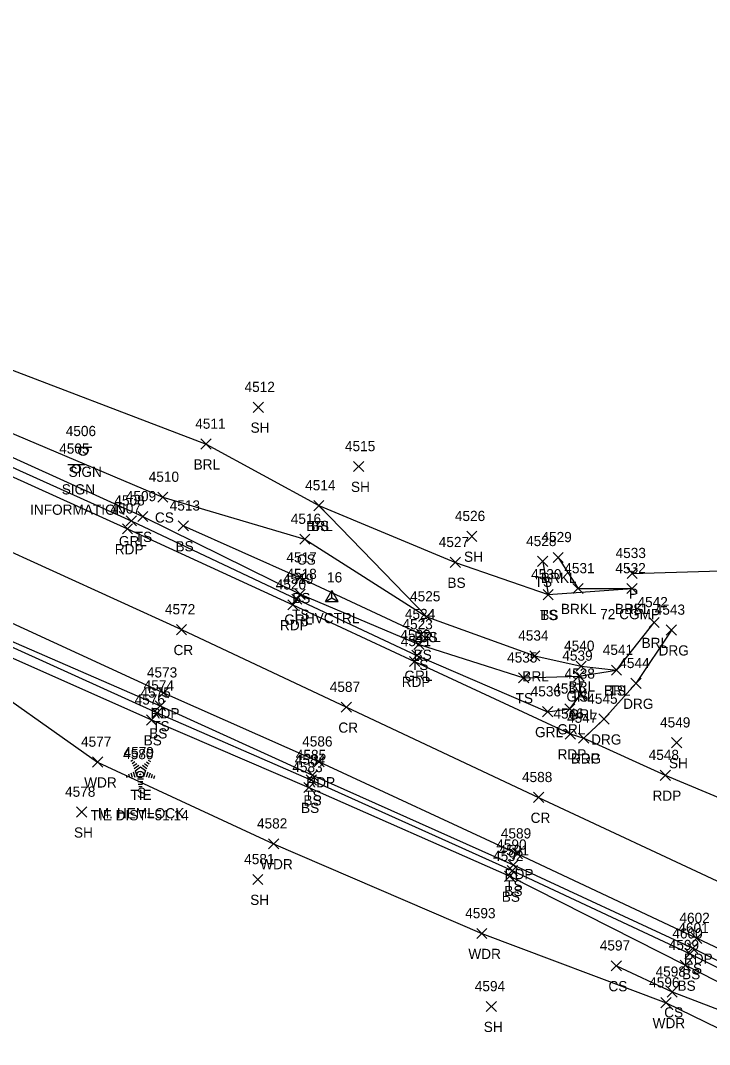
# Model space of a CAD drawing. Extents: x 1611797 to 1633212, y 298978 to 305475.
# Drawn here: x 1619568.2 to 1619703.4, y 301313.3 to 301514.2 of the extents above; entities that cross this region are included whole.
import ezdxf

# ---------------------------------------------------------------- set-up
doc = ezdxf.new("R2010")
doc.units = 0
for name, color, linetype in [('C_A', 7, 'Continuous'), ('C_C', 7, 'Continuous'), ('C_I', 7, 'Continuous'), ('CBP', 7, 'Continuous'), ('CPSM', 7, 'Continuous'), ('D_A', 7, 'Continuous'), ('D_C', 7, 'Continuous'), ('D_I', 7, 'Continuous'), ('D_TIC', 7, 'Continuous'), ('DCP', 7, 'Continuous'), ('L_A', 7, 'Continuous'), ('L_C', 7, 'Continuous'), ('L_I', 7, 'Continuous'), ('L_TIC', 7, 'Continuous'), ('LABL', 7, 'Continuous'), ('LAWA', 7, 'Continuous'), ('LAWE', 7, 'Continuous'), ('LELB', 7, 'Continuous'), ('LTC', 7, 'Continuous'), ('P_A', 7, 'Continuous'), ('P_I', 7, 'Continuous'), ('P_TIC', 7, 'Continuous'), ('PET', 7, 'Continuous'), ('PRC', 7, 'Continuous'), ('R_A', 7, 'Continuous'), ('R_I', 7, 'Continuous'), ('R_TIC', 7, 'Continuous'), ('RDG', 7, 'Continuous'), ('RGR', 7, 'Continuous'), ('S_A', 7, 'Continuous'), ('S_C', 7, 'Continuous'), ('S_I', 7, 'Continuous'), ('SSGN', 7, 'Continuous')]:
    doc.layers.add(name, color=color, linetype=linetype)

msp = doc.modelspace()

# ---------------------------------------------------------------- linework, layer by layer
at = {"layer": 'CBP'}
for radius in [0.625, 0.0833]:
    msp.add_circle((1619591.7, 301366.28), radius, dxfattribs=at)
at = {"layer": 'CPSM'}
for p, q in [((1619628.05, 301400.23), (1619629.3, 301402.39)), ((1619630.55, 301400.23), (1619629.3, 301402.39)), ((1619629.3, 301400.95), (1619629.3, 301402.39)), ((1619628.05, 301400.23), (1619629.3, 301400.95)), ((1619628.05, 301400.23), (1619630.55, 301400.23)), ((1619629.3, 301400.95), (1619629.3, 301400.95)), ((1619629.3, 301400.95), (1619630.55, 301400.23))]:
    msp.add_line(p, q, dxfattribs=at)
at = {"layer": 'D_TIC'}
for points in [[(1619687.22, 301404.73), (1619689.22, 301406.73)], [(1619689.22, 301404.73), (1619687.22, 301406.73)]]:
    msp.add_lwpolyline(points, dxfattribs=at)
at = {"layer": 'DCP'}
msp.add_lwpolyline([(1619688.22, 301405.73), (1619718.54, 301406.6)], dxfattribs=at)
at = {"layer": 'L_TIC'}
for points in [[(1619613.87, 301437.31), (1619615.87, 301439.31)], [(1619615.87, 301437.31), (1619613.87, 301439.31)], [(1619603.62, 301430.09), (1619605.62, 301432.09)], [(1619605.62, 301430.09), (1619603.62, 301432.09)], [(1619633.56, 301425.69), (1619635.56, 301427.69)], [(1619635.56, 301425.69), (1619633.56, 301427.69)], [(1619595.15, 301419.68), (1619597.15, 301421.68)], [(1619597.15, 301419.68), (1619595.15, 301421.68)], [(1619625.75, 301418.02), (1619627.75, 301420.02)], [(1619627.75, 301418.02), (1619625.75, 301420.02)], [(1619625.75, 301418.02), (1619627.75, 301420.02)], [(1619627.75, 301418.02), (1619625.75, 301420.02)], [(1619591.22, 301415.88), (1619593.22, 301417.88)], [(1619593.22, 301415.88), (1619591.22, 301417.88)], [(1619599.18, 301414.04), (1619601.18, 301416.04)], [(1619601.18, 301414.04), (1619599.18, 301416.04)], [(1619655.75, 301411.99), (1619657.75, 301413.99)], [(1619657.75, 301411.99), (1619655.75, 301413.99)], [(1619622.99, 301411.43), (1619624.99, 301413.43)], [(1619624.99, 301411.43), (1619622.99, 301413.43)], [(1619672.69, 301407.85), (1619674.69, 301409.85)], [(1619674.69, 301407.85), (1619672.69, 301409.85)], [(1619652.53, 301406.88), (1619654.53, 301408.88)], [(1619654.53, 301406.88), (1619652.53, 301408.88)], [(1619669.67, 301407.07), (1619671.67, 301409.07)], [(1619671.67, 301407.07), (1619669.67, 301409.07)], [(1619622.08, 301403.88), (1619624.08, 301405.88)], [(1619624.08, 301403.88), (1619622.08, 301405.88)], [(1619676.59, 301401.75), (1619678.59, 301403.75)], [(1619678.59, 301401.75), (1619676.59, 301403.75)], [(1619687.19, 301401.75), (1619689.19, 301403.75)], [(1619689.19, 301401.75), (1619687.19, 301403.75)], [(1619687.19, 301401.75), (1619689.19, 301403.75)], [(1619689.19, 301401.75), (1619687.19, 301403.75)], [(1619622.08, 301400.62), (1619624.08, 301402.62)], [(1619624.08, 301400.62), (1619622.08, 301402.62)], [(1619670.74, 301400.56), (1619672.74, 301402.56)], [(1619672.74, 301400.56), (1619670.74, 301402.56)], [(1619670.74, 301400.56), (1619672.74, 301402.56)], [(1619672.74, 301400.56), (1619670.74, 301402.56)], [(1619646.9, 301396.23), (1619648.9, 301398.23)], [(1619648.9, 301396.23), (1619646.9, 301398.23)], [(1619646.9, 301396.23), (1619648.9, 301398.23)], [(1619648.9, 301396.23), (1619646.9, 301398.23)], [(1619691.52, 301395.09), (1619693.52, 301397.09)], [(1619693.52, 301395.09), (1619691.52, 301397.09)], [(1619645.89, 301392.76), (1619647.89, 301394.76)], [(1619647.89, 301392.76), (1619645.89, 301394.76)], [(1619645.41, 301390.76), (1619647.41, 301392.76)], [(1619647.41, 301390.76), (1619645.41, 301392.76)], [(1619668.12, 301388.54), (1619670.12, 301390.54)], [(1619670.12, 301388.54), (1619668.12, 301390.54)], [(1619677.21, 301386.53), (1619679.21, 301388.53)], [(1619679.21, 301386.53), (1619677.21, 301388.53)], [(1619684.14, 301385.73), (1619686.14, 301387.73)], [(1619686.14, 301385.73), (1619684.14, 301387.73)], [(1619684.14, 301385.73), (1619686.14, 301387.73)], [(1619686.14, 301385.73), (1619684.14, 301387.73)], [(1619665.94, 301384.23), (1619667.94, 301386.23)], [(1619667.94, 301384.23), (1619665.94, 301386.23)], [(1619676.78, 301384.59), (1619678.78, 301386.59)], [(1619678.78, 301384.59), (1619676.78, 301386.59)], [(1619594.64, 301378.74), (1619596.64, 301380.74)], [(1619596.64, 301378.74), (1619594.64, 301380.74)], [(1619592.93, 301375.98), (1619594.93, 301377.98)], [(1619594.93, 301375.98), (1619592.93, 301377.98)], [(1619594.01, 301377.34), (1619596.01, 301379.34)], [(1619596.01, 301377.34), (1619594.01, 301379.34)], [(1619695.95, 301371.5), (1619697.95, 301373.5)], [(1619697.95, 301371.5), (1619695.95, 301373.5)], [(1619582.35, 301367.71), (1619584.35, 301369.71)], [(1619584.35, 301367.71), (1619582.35, 301369.71)], [(1619624.28, 301364.19), (1619626.28, 301366.19)], [(1619626.28, 301364.19), (1619624.28, 301366.19)], [(1619624.49, 301365.11), (1619626.49, 301367.11)], [(1619626.49, 301365.11), (1619624.49, 301367.11)], [(1619623.81, 301362.73), (1619625.81, 301364.73)], [(1619625.81, 301362.73), (1619623.81, 301364.73)], [(1619579.22, 301357.9), (1619581.22, 301359.9)], [(1619581.22, 301357.9), (1619579.22, 301359.9)], [(1619616.87, 301351.68), (1619618.87, 301353.68)], [(1619618.87, 301351.68), (1619616.87, 301353.68)], [(1619663.9, 301347.53), (1619665.9, 301349.53)], [(1619665.9, 301347.53), (1619663.9, 301349.53)], [(1619663.7, 301346.42), (1619665.7, 301348.42)], [(1619665.7, 301346.42), (1619663.7, 301348.42)], [(1619613.79, 301344.68), (1619615.79, 301346.68)], [(1619615.79, 301344.68), (1619613.79, 301346.68)], [(1619663.19, 301345.3), (1619665.19, 301347.3)], [(1619665.19, 301345.3), (1619663.19, 301347.3)], [(1619657.72, 301334.08), (1619659.72, 301336.08)], [(1619659.72, 301334.08), (1619657.72, 301336.08)], [(1619698.56, 301330.11), (1619700.56, 301332.11)], [(1619700.56, 301330.11), (1619698.56, 301332.11)], [(1619699.1, 301331.19), (1619701.1, 301333.19)], [(1619701.1, 301331.19), (1619699.1, 301333.19)], [(1619684.12, 301327.75), (1619686.12, 301329.75)], [(1619686.12, 301327.75), (1619684.12, 301329.75)], [(1619697.66, 301327.84), (1619699.66, 301329.84)], [(1619699.66, 301327.84), (1619697.66, 301329.84)], [(1619695.06, 301322.61), (1619697.06, 301324.61)], [(1619697.06, 301322.61), (1619695.06, 301324.61)], [(1619659.6, 301319.76), (1619661.6, 301321.76)], [(1619661.6, 301319.76), (1619659.6, 301321.76)], [(1619693.86, 301320.5), (1619695.86, 301322.5)], [(1619695.86, 301320.5), (1619693.86, 301322.5)]]:
    msp.add_lwpolyline(points, dxfattribs=at)
at = {"layer": 'LABL'}
msp.add_lwpolyline([(1619559.36, 301448.36), (1619604.62, 301431.09), (1619626.75, 301419.02), (1619647.9, 301397.23), (1619669.12, 301389.54), (1619678.21, 301387.53), (1619685.14, 301386.73), (1619692.52, 301396.09)], dxfattribs=at)
at = {"layer": 'LAWA'}
msp.add_lwpolyline([(1619507.86, 301398.95), (1619518.08, 301400.79), (1619556.65, 301387.52), (1619583.35, 301368.71), (1619617.87, 301352.68), (1619658.72, 301335.08), (1619694.86, 301321.5), (1619725.46, 301306.6), (1619750.78, 301288.01), (1619784.9, 301274.32), (1619812.4, 301257.15), (1619844.1, 301250.77), (1619874.95, 301250.41), (1619914.22, 301239.23), (1619945.35, 301230.93), (1619986.13, 301221.13), (1620021.48, 301214.73), (1620067.45, 301208.49), (1620101.58, 301197.67), (1620125.21, 301192.85)], dxfattribs=at)
at = {"layer": 'LAWE'}
msp.add_lwpolyline([(1619673.69, 301408.85), (1619677.59, 301402.75), (1619688.19, 301402.75)], dxfattribs=at)
at = {"layer": 'LELB'}
for points in [[(1619374.24, 301514.17), (1619396.45, 301504.93), (1619440.64, 301484.21), (1619465.66, 301473.55), (1619491.73, 301461.64), (1619517.36, 301453.25), (1619539.79, 301440.1), (1619561.74, 301430.67), (1619592.22, 301416.88), (1619623.08, 301401.62), (1619646.41, 301391.76), (1619666.94, 301385.23), (1619677.78, 301385.59), (1619685.14, 301386.73)], [(1619350.31, 301489.81), (1619380.89, 301476.99), (1619406.21, 301465.78), (1619425.96, 301458.32), (1619457.01, 301443.93), (1619488.18, 301429.04), (1619515.79, 301415.84), (1619523.25, 301412.34), (1619557.22, 301396.43), (1619595.64, 301379.74), (1619625.49, 301366.11), (1619664.9, 301348.53), (1619700.1, 301332.19), (1619732.76, 301315.82), (1619759.48, 301302.13), (1619789.83, 301287.62), (1619820.2, 301275.83), (1619850.42, 301266.87), (1619878.56, 301257.32), (1619912.05, 301251.69), (1619947.78, 301244.54), (1619986.64, 301235.92)], [(1619541.09, 301445.72), (1619563.52, 301434.46), (1619596.15, 301420.68), (1619623.99, 301412.43), (1619647.9, 301397.23)], [(1619626.75, 301419.02), (1619653.53, 301407.88), (1619671.74, 301401.56), (1619688.19, 301402.75)], [(1619515.86, 301413.84), (1619522.39, 301411.67), (1619557.04, 301395.57), (1619595.01, 301378.34), (1619625.28, 301365.19), (1619664.7, 301347.42), (1619699.56, 301331.11), (1619732.26, 301314.67), (1619758.81, 301300.85), (1619789.23, 301285.42), (1619819.18, 301274.31), (1619849.56, 301265.07), (1619878.74, 301254.24), (1619911.39, 301248.67), (1619947.63, 301242.31), (1619986.12, 301232.79)], [(1619600.18, 301415.04), (1619623.08, 301404.88), (1619646.89, 301393.76)], [(1619514.13, 301412.04), (1619521.16, 301409.66), (1619556.07, 301393.79), (1619593.93, 301376.98), (1619624.81, 301363.73), (1619664.19, 301346.3), (1619698.66, 301328.84), (1619731.18, 301312.27), (1619757.56, 301299.07), (1619788.59, 301282.92), (1619818.22, 301271.64), (1619848.03, 301261.72), (1619876.44, 301251.78), (1619910.7, 301243.48), (1619946.63, 301234.74), (1619971.5, 301227.31), (1619985.16, 301225.14), (1620021.48, 301214.73)], [(1619670.67, 301408.07), (1619671.74, 301401.56)], [(1619685.12, 301328.75), (1619696.06, 301323.61), (1619730.59, 301310.45), (1619756.56, 301297.34), (1619787.5, 301280.33), (1619817.39, 301268.62), (1619845.61, 301256.67), (1619874.95, 301250.41)]]:
    msp.add_lwpolyline(points, dxfattribs=at)
at = {"layer": 'LTC'}
for p, q in [((1619589.89, 301368.87), (1619590.24, 301369.13)), ((1619590.1, 301368.41), (1619590.63, 301368.79)), ((1619590.31, 301367.94), (1619591.01, 301368.45)), ((1619590.52, 301367.48), (1619591.4, 301368.12)), ((1619590.74, 301367.02), (1619591.75, 301367.76)), ((1619591.75, 301367.76), (1619592.75, 301367.03)), ((1619592.17, 301368.07), (1619592.98, 301367.48)), ((1619592.55, 301368.42), (1619593.23, 301367.92)), ((1619592.92, 301368.77), (1619593.47, 301368.37)), ((1619593.29, 301369.11), (1619593.71, 301368.81)), ((1619588.92, 301366.15), (1619589.07, 301365.69)), ((1619589.38, 301366.37), (1619589.59, 301365.72)), ((1619589.83, 301366.59), (1619590.1, 301365.75)), ((1619590.29, 301366.8), (1619590.62, 301365.78)), ((1619590.74, 301367.02), (1619591.13, 301365.83)), ((1619592.36, 301365.83), (1619591.13, 301365.83)), ((1619592.75, 301367.03), (1619592.36, 301365.83)), ((1619593.19, 301366.76), (1619592.85, 301365.72)), ((1619593.63, 301366.51), (1619593.35, 301365.63)), ((1619594.08, 301366.26), (1619593.84, 301365.53)), ((1619594.52, 301366.01), (1619594.34, 301365.44)), ((1619592.32, 301365.33), (1619591.18, 301365.33)), ((1619592.24, 301364.83), (1619591.25, 301364.83)), ((1619592.15, 301364.33), (1619591.32, 301364.33)), ((1619592.07, 301363.83), (1619591.4, 301363.83))]:
    msp.add_line(p, q, dxfattribs=at)
at = {"layer": 'P_TIC'}
for points in [[(1619588.22, 301413.46), (1619590.22, 301415.46)], [(1619590.22, 301413.46), (1619588.22, 301415.46)], [(1619620.64, 301398.56), (1619622.64, 301400.56)], [(1619622.64, 301398.56), (1619620.64, 301400.56)], [(1619598.81, 301393.69), (1619600.81, 301395.69)], [(1619600.81, 301393.69), (1619598.81, 301395.69)], [(1619644.53, 301387.44), (1619646.53, 301389.44)], [(1619646.53, 301387.44), (1619644.53, 301389.44)], [(1619595.27, 301381.3), (1619597.27, 301383.3)], [(1619597.27, 301381.3), (1619595.27, 301383.3)], [(1619631.15, 301378.47), (1619633.15, 301380.47)], [(1619633.15, 301378.47), (1619631.15, 301380.47)], [(1619675.08, 301373.23), (1619677.08, 301375.23)], [(1619677.08, 301373.23), (1619675.08, 301375.23)], [(1619677.71, 301372.41), (1619679.71, 301374.41)], [(1619679.71, 301372.41), (1619677.71, 301374.41)], [(1619625.79, 301367.76), (1619627.79, 301369.76)], [(1619627.79, 301367.76), (1619625.79, 301369.76)], [(1619693.71, 301365.12), (1619695.71, 301367.12)], [(1619695.71, 301365.12), (1619693.71, 301367.12)], [(1619668.86, 301360.78), (1619670.86, 301362.78)], [(1619670.86, 301360.78), (1619668.86, 301362.78)], [(1619664.72, 301349.73), (1619666.72, 301351.73)], [(1619666.72, 301349.73), (1619664.72, 301351.73)], [(1619699.87, 301333.15), (1619701.87, 301335.15)], [(1619701.87, 301333.15), (1619699.87, 301335.15)]]:
    msp.add_lwpolyline(points, dxfattribs=at)
at = {"layer": 'PET'}
for points in [[(1619561.18, 301427.13), (1619589.22, 301414.46), (1619621.64, 301399.56), (1619645.53, 301388.44), (1619676.08, 301374.23), (1619678.71, 301373.41), (1619694.71, 301366.12), (1619710.67, 301359.44), (1619714.46, 301356.51), (1619735.11, 301346.33), (1619783.71, 301324.55), (1619832.02, 301304.42), (1619849.55, 301298.27), (1619870.41, 301291.84), (1619910.7, 301281.21), (1619950.83, 301272.88), (1619994.49, 301265.52)], [(1619558.04, 301399.85), (1619596.27, 301382.3), (1619626.79, 301368.76), (1619665.72, 301350.73), (1619700.87, 301334.15), (1619733.81, 301318.69), (1619761.36, 301305.85), (1619791.6, 301292.8), (1619823.48, 301280.05), (1619851.63, 301270.31), (1619880.36, 301262.32), (1619912.48, 301254.3), (1619949.02, 301246.88), (1619987.97, 301240.43)]]:
    msp.add_lwpolyline(points, dxfattribs=at)
at = {"layer": 'PRC'}
msp.add_lwpolyline([(1619561.88, 301411.99), (1619599.81, 301394.69), (1619632.15, 301379.47), (1619669.86, 301361.78), (1619706.8, 301344.47), (1619738.62, 301329.48), (1619766.38, 301316.26), (1619796.53, 301303.45), (1619827.59, 301291.15), (1619854.63, 301281.96), (1619882.39, 301274.22), (1619915.66, 301266.28), (1619950.93, 301259.45), (1619990.95, 301252.78)], dxfattribs=at)
at = {"layer": 'R_TIC'}
for points in [[(1619588.96, 301415.04), (1619590.96, 301417.04)], [(1619590.96, 301415.04), (1619588.96, 301417.04)], [(1619621.43, 301399.67), (1619623.43, 301401.67)], [(1619623.43, 301399.67), (1619621.43, 301401.67)], [(1619694.9, 301393.61), (1619696.9, 301395.61)], [(1619696.9, 301393.61), (1619694.9, 301395.61)], [(1619645, 301388.64), (1619647, 301390.64)], [(1619647, 301388.64), (1619645, 301390.64)], [(1619676.78, 301384.59), (1619678.78, 301386.59)], [(1619678.78, 301384.59), (1619676.78, 301386.59)], [(1619687.95, 301383.14), (1619689.95, 301385.14)], [(1619689.95, 301383.14), (1619687.95, 301385.14)], [(1619677.21, 301381.07), (1619679.21, 301383.07)], [(1619679.21, 301381.07), (1619677.21, 301383.07)], [(1619670.62, 301377.59), (1619672.62, 301379.59)], [(1619672.62, 301377.59), (1619670.62, 301379.59)], [(1619674.99, 301378.14), (1619676.99, 301380.14)], [(1619676.99, 301378.14), (1619674.99, 301380.14)], [(1619681.67, 301376.14), (1619683.67, 301378.14)], [(1619683.67, 301376.14), (1619681.67, 301378.14)], [(1619677.71, 301372.41), (1619679.71, 301374.41)], [(1619679.71, 301372.41), (1619677.71, 301374.41)]]:
    msp.add_lwpolyline(points, dxfattribs=at)
at = {"layer": 'RDG'}
msp.add_lwpolyline([(1619695.9, 301394.61), (1619688.95, 301384.14), (1619682.67, 301377.14), (1619678.71, 301373.41)], dxfattribs=at)
at = {"layer": 'RGR'}
msp.add_lwpolyline([(1619561.3, 301428.91), (1619589.96, 301416.04), (1619622.43, 301400.67), (1619646, 301389.64), (1619671.62, 301378.59), (1619675.99, 301379.14), (1619678.21, 301382.07), (1619677.78, 301385.59)], dxfattribs=at)
at = {"layer": 'SSGN'}
for p, q in [((1619578.86, 301430.5), (1619582.19, 301430.5)), ((1619580.5, 301429.67), (1619580.5, 301429.67)), ((1619577.52, 301427.07), (1619580.85, 301427.07)), ((1619579.17, 301426.23), (1619579.17, 301426.23))]:
    msp.add_line(p, q, dxfattribs=at)
for centre in [(1619580.5, 301429.67), (1619579.17, 301426.23)]:
    msp.add_circle(centre, 0.833, dxfattribs=at)

# ---------------------------------------------------------------- texts
at = {"layer": 'C_A'}
for s, p in [('HVCTRL', (1619624, 301395.95)), ('TIE', (1619589.78, 301361.28))]:
    msp.add_text(s, height=2, dxfattribs=at).set_placement(p)
at = {"layer": 'C_C'}
msp.add_text('TIE DIST=51.14', height=2, dxfattribs=at).set_placement((1619581.97, 301357.28))
at = {"layer": 'C_I'}
for s, p in [('16', (1619628.35, 301403.95)), ('4580', (1619588.36, 301369.28))]:
    msp.add_text(s, height=2, dxfattribs=at).set_placement(p)
at = {"layer": 'D_A'}
msp.add_text('P', height=2, dxfattribs=at).set_placement((1619687.6, 301400.73))
at = {"layer": 'D_C'}
msp.add_text('72 CGMP', height=2, dxfattribs=at).set_placement((1619681.94, 301396.73))
at = {"layer": 'D_I'}
msp.add_text('4533', height=2, dxfattribs=at).set_placement((1619684.96, 301408.73))
at = {"layer": 'L_A'}
for s, p in [('SH', (1619613.35, 301433.31)), ('BRL', (1619602.17, 301426.09)), ('SH', (1619633.05, 301421.69)), ('CS', (1619594.59, 301415.68)), ('BRL', (1619624.3, 301414.02)), ('BS', (1619625.19, 301414.02)), ('TS', (1619590.63, 301411.88)), ('BS', (1619598.62, 301410.04)), ('SH', (1619655.23, 301407.99)), ('CS', (1619622.43, 301407.43)), ('BRKL', (1619670.33, 301403.85)), ('BS', (1619651.97, 301402.88)), ('TS', (1619669.08, 301403.07)), ('BS', (1619621.52, 301399.88)), ('BRKL', (1619674.24, 301397.75)), ('BRKL', (1619684.84, 301397.75)), ('BS', (1619686.63, 301397.75)), ('TS', (1619621.49, 301396.62)), ('TS', (1619670.15, 301396.56)), ('BS', (1619670.18, 301396.56)), ('BRL', (1619645.44, 301392.23)), ('CS', (1619646.34, 301392.23)), ('BRL', (1619690.06, 301391.09)), ('BS', (1619645.33, 301388.76)), ('TS', (1619644.82, 301386.76)), ('BRL', (1619666.67, 301384.54)), ('BRL', (1619675.75, 301382.53)), ('BRL', (1619682.69, 301381.73)), ('TS', (1619683.55, 301381.73)), ('TS', (1619665.35, 301380.23)), ('TS', (1619676.19, 301380.59)), ('TS', (1619594.05, 301374.74)), ('BS', (1619592.37, 301371.98)), ('BS', (1619593.45, 301373.34)), ('SH', (1619695.43, 301367.5)), ('WDR', (1619580.71, 301363.71)), ('S', (1619591.08, 301361.67)), ('BS', (1619623.72, 301360.19)), ('TS', (1619623.9, 301361.11)), ('BS', (1619623.25, 301358.73)), ('SH', (1619578.71, 301353.9)), ('WDR', (1619615.24, 301347.68)), ('TS', (1619663.31, 301343.53)), ('BS', (1619662.63, 301341.3)), ('BS', (1619663.14, 301342.42)), ('SH', (1619613.28, 301340.68)), ('WDR', (1619656.08, 301330.08)), ('BS', (1619698, 301326.11)), ('TS', (1619698.51, 301327.19)), ('CS', (1619683.56, 301323.75)), ('BS', (1619697.1, 301323.84)), ('CS', (1619694.5, 301318.61)), ('SH', (1619659.09, 301315.76)), ('WDR', (1619692.22, 301316.5))]:
    msp.add_text(s, height=2, dxfattribs=at).set_placement(p)
at = {"layer": 'L_C'}
msp.add_text('M. HEMLOCK', height=2, dxfattribs=at).set_placement((1619583.4, 301357.67))
at = {"layer": 'L_I'}
for s, p in [('4512', (1619612.17, 301441.31)), ('4511', (1619602.5, 301434.09)), ('4515', (1619631.87, 301429.69)), ('4510', (1619593.37, 301423.68)), ('4514', (1619624.06, 301422.02)), ('4514', (1619624.06, 301422.02)), ('4509', (1619588.88, 301419.88)), ('4513', (1619597.49, 301418.04)), ('4526', (1619653.43, 301415.99)), ('4516', (1619621.24, 301415.43)), ('4529', (1619670.42, 301411.85)), ('4527', (1619650.27, 301410.88)), ('4528', (1619667.41, 301411.07)), ('4517', (1619620.38, 301407.88)), ('4531', (1619674.9, 301405.75)), ('4532', (1619684.93, 301405.75)), ('4532', (1619684.93, 301405.75)), ('4518', (1619620.39, 301404.62)), ('4530', (1619668.39, 301404.56)), ('4530', (1619668.39, 301404.56)), ('4525', (1619644.64, 301400.23)), ('4525', (1619644.64, 301400.23)), ('4542', (1619689.26, 301399.09)), ('4524', (1619643.63, 301396.76)), ('4523', (1619643.15, 301394.76)), ('4534', (1619665.86, 301392.54)), ('4540', (1619674.86, 301390.53)), ('4541', (1619682.45, 301389.73)), ('4541', (1619682.45, 301389.73)), ('4535', (1619663.68, 301388.23)), ('4539', (1619674.51, 301388.59)), ('4574', (1619592.38, 301382.74)), ('4576', (1619590.61, 301379.98)), ('4575', (1619591.75, 301381.34)), ('4549', (1619693.68, 301375.5)), ('4577', (1619580.09, 301371.71)), ('4579', (1619588.43, 301369.67)), ('4584', (1619622.02, 301368.19)), ('4585', (1619622.23, 301369.11)), ('4583', (1619621.55, 301366.73)), ('4578', (1619576.96, 301361.9)), ('4582', (1619614.61, 301355.68)), ('4590', (1619661.55, 301351.53)), ('4591', (1619662.01, 301350.42)), ('4581', (1619612.1, 301348.68)), ('4592', (1619660.93, 301349.3)), ('4593', (1619655.46, 301338.08)), ('4600', (1619696.09, 301334.11)), ('4601', (1619697.28, 301335.19)), ('4597', (1619681.86, 301331.75)), ('4599', (1619695.39, 301331.84)), ('4598', (1619692.8, 301326.61)), ('4594', (1619657.34, 301323.76)), ('4596', (1619691.55, 301324.5))]:
    msp.add_text(s, height=2, dxfattribs=at).set_placement(p)
at = {"layer": 'LTC'}
msp.add_text('.', height=1.04, rotation=270, dxfattribs=at).set_placement((1619591.64, 301366.77))
at = {"layer": 'P_A'}
for s, p in [('RDP', (1619586.71, 301409.46)), ('RDP', (1619619.12, 301394.56)), ('CR', (1619598.24, 301389.69)), ('RDP', (1619643.01, 301383.44)), ('RDP', (1619593.76, 301377.3)), ('CR', (1619630.58, 301374.47)), ('RDP', (1619673.57, 301369.23)), ('RDP', (1619676.19, 301368.41)), ('RDP', (1619624.28, 301363.76)), ('RDP', (1619692.2, 301361.12)), ('CR', (1619668.29, 301356.78)), ('RDP', (1619663.21, 301345.73)), ('RDP', (1619698.36, 301329.15))]:
    msp.add_text(s, height=2, dxfattribs=at).set_placement(p)
at = {"layer": 'P_I'}
for s, p in [('4507', (1619585.89, 301417.46)), ('4520', (1619618.29, 301402.56)), ('4572', (1619596.55, 301397.69)), ('4521', (1619642.83, 301391.44)), ('4573', (1619593.01, 301385.3)), ('4587', (1619628.89, 301382.47)), ('4546', (1619672.77, 301377.23)), ('4547', (1619675.45, 301376.41)), ('4586', (1619623.48, 301371.76)), ('4548', (1619691.45, 301369.12)), ('4588', (1619666.6, 301364.78)), ('4589', (1619662.45, 301353.73)), ('4602', (1619697.49, 301337.15))]:
    msp.add_text(s, height=2, dxfattribs=at).set_placement(p)
at = {"layer": 'R_A'}
for s, p in [('GRL', (1619587.51, 301411.04)), ('GRL', (1619619.97, 301395.67)), ('DRG', (1619693.39, 301389.61)), ('GRL', (1619643.54, 301384.64)), ('GRL', (1619675.32, 301380.59)), ('DRG', (1619686.44, 301379.14)), ('GRL', (1619675.76, 301377.07)), ('GRL', (1619669.16, 301373.59)), ('GRL', (1619673.53, 301374.14)), ('DRG', (1619680.16, 301372.14)), ('DRG', (1619676.19, 301368.41))]:
    msp.add_text(s, height=2, dxfattribs=at).set_placement(p)
at = {"layer": 'R_I'}
for s, p in [('4508', (1619586.63, 301419.04)), ('4519', (1619619.73, 301403.67)), ('4543', (1619692.64, 301397.61)), ('4522', (1619642.74, 301392.64)), ('4539', (1619674.51, 301388.59)), ('4544', (1619685.69, 301387.14)), ('4538', (1619674.95, 301385.07)), ('4536', (1619668.31, 301381.59)), ('4537', (1619672.73, 301382.14)), ('4545', (1619679.41, 301380.14)), ('4547', (1619675.45, 301376.41))]:
    msp.add_text(s, height=2, dxfattribs=at).set_placement(p)
at = {"layer": 'S_A'}
for p in [(1619577.64, 301424.65), (1619576.31, 301421.21)]:
    msp.add_text('SIGN', height=2, dxfattribs=at).set_placement(p)
at = {"layer": 'S_C'}
msp.add_text('INFORMATION', height=2, dxfattribs=at).set_placement((1619570.1, 301417.21))
at = {"layer": 'S_I'}
for s, p in [('4506', (1619577.09, 301432.65)), ('4505', (1619575.81, 301429.21))]:
    msp.add_text(s, height=2, dxfattribs=at).set_placement(p)

doc.saveas('drawing.dxf')
